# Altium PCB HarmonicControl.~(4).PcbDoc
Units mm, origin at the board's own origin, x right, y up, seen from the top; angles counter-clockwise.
Board outline 133.86 x 40.01 mm, 2 copper layers (Top Layer, Bottom Layer); 10 components, 14 nets, 56 pads, 1 vias.
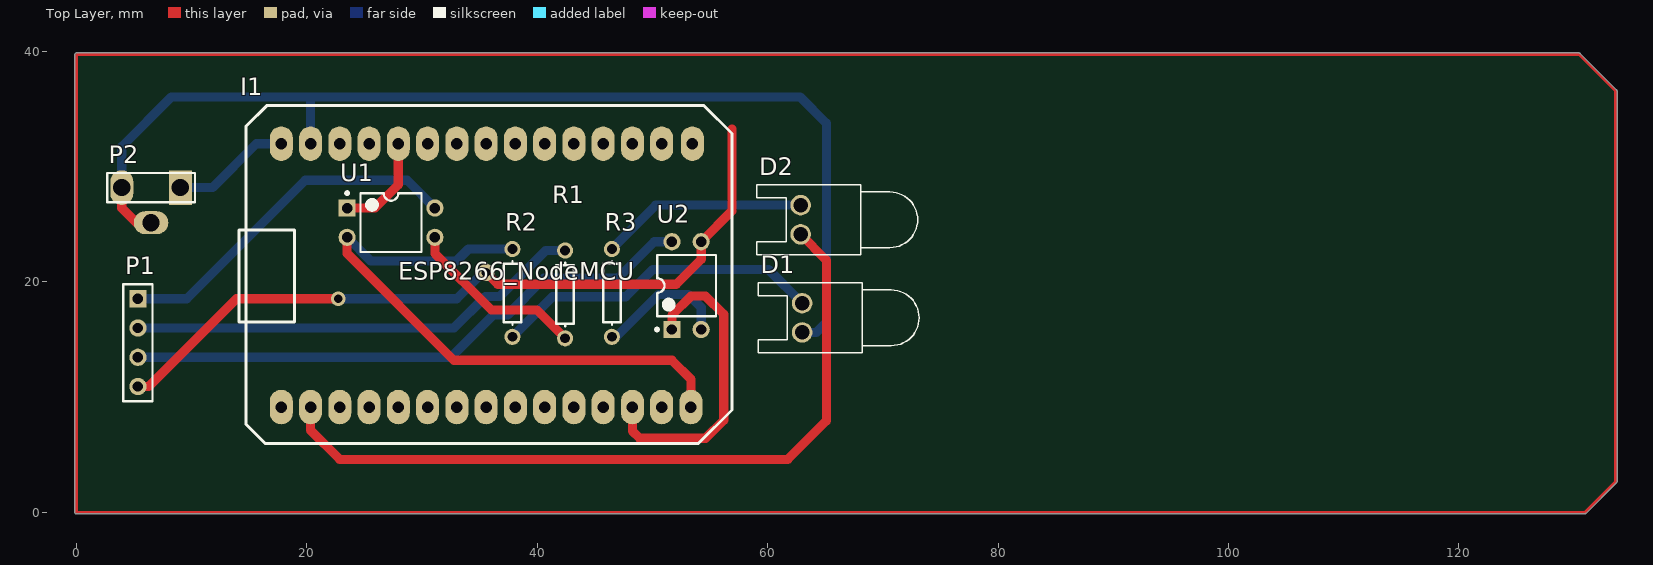
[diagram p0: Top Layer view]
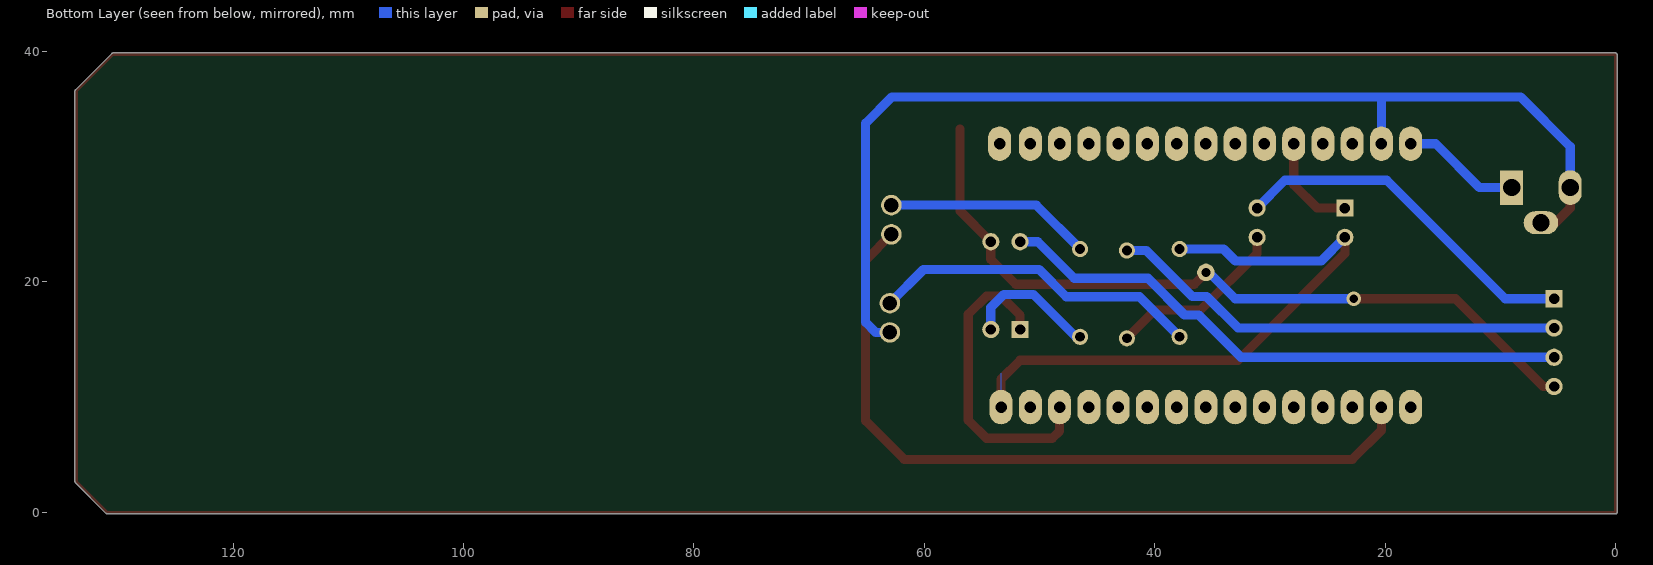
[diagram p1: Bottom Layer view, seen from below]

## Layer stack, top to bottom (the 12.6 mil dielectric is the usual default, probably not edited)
Top Solder: solder mask 0.0102, Solder Resist, Dk 3.5
Top Layer: signal copper 0.0356
Dielectric 1: dielectric 0.32, FR-4, Dk 4.8
Bottom Layer: signal copper 0.0356
Bottom Solder: solder mask 0.0102, Solder Resist, Dk 3.5

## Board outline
0.064,-0.11 cw(c0,0) -0.127,0 -0.127,39.751 cw(c0,39.751) 0,39.878 130.429,39.878 cw(c130.429,39.751) 130.52,39.841 130.519,39.841 133.694,36.666 133.694,36.667 cw(c133.604,36.576) 133.731,36.576 133.731,2.667 cw(c133.604,2.667) 133.694,2.576 133.694,2.577 131.027,-0.09 131.028,-0.09 cw(c130.937,0) 130.937,-0.127 0.127,-0.127 cw(c0.127,0)

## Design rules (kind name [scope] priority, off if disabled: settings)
Clearance [All] p1: gap=0.8 ignorepadtopadclearanceinfootprint=FALSE
PolygonConnect [All] p1: connectstyle=Relief reliefconductorwidth=0.254 reliefentries=4 polygonreliefangle="90 Angle" airgapwidth=0.254
RoutingVias [All] p1: holewidth=0.711 width=1.27 viastyle="Through Hole" minholewidth=0.711 minwidth=1.27 maxholewidth=0.711 maxwidth=1.27
SolderMaskExpansion [All] p1: expansion=0.102
Width [All] p1: maxlimit=1 minlimit=0.5 preferedwidth=0.8
30 further rules are at their usual default settings.

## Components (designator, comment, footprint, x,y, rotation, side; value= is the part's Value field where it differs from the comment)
D1 "LED0" LED-0 62.992,16.891 r90 top
D2 "LED0" LED-0 62.865,25.4 r90 top
I1 "ESP8266" ESP8266_Node_MCU_V3 17.78,32.004 r270 top
P1 "Cable" HDR1X4 5.334,18.542 r270 top
P2 "Jack3.5mm" HDR1X3 9.017,28.194 r180 top
R1 "Res1" AXIAL-0.3 42.418,18.923 r90 top value=1K
R2 "Res1" AXIAL-0.3 37.846,19.05 r270 top value=1K
R3 "Res1" AXIAL-0.3 46.482,19.05 r270 top value=1K
U1 "InputSignal" DIP-4 27.305,25.146 r0 top
U2 "Output_Control" DIP-4 52.959,19.685 r90 top

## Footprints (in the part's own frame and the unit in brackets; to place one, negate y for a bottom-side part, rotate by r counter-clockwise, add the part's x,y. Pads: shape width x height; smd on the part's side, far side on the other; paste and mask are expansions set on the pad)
AXIAL-0.3 [mm] "Axial Device, Thru-Hole; 2 Leads; 0.3 in Pin Spacing"
  round 1.4 hole 0.85: 1(-3.81,0) 2(3.81,0)
  silkscreen extent -2.77,-0.76 2.77,0.76
DIP-4 [mm] "DIP; 4 Leads; Row Spacing 7.62 mm; Pitch 2.54 mm"
  rect 1.5x1.5 hole 0.9: 1(-3.81,1.27)
  round 1.5 hole 0.9: 2(-3.81,-1.27) 3(3.81,-1.27) 4(3.81,1.27)
  silkscreen extent -3.93,-2.55 2.65,2.69, body extent -3.15,-2.5 3.15,2.5, height 5.6
ESP8266_Node_MCU_V3 [mm]
  oval 3x2 hole 1 paste+0 mask+0.102: 1(22.86,35.56) 2(22.86,33.02) 3(22.86,30.48) 4(22.86,27.94) 5(22.86,25.4) 6(22.86,22.86) 7(22.86,20.32) 8(22.86,17.78) 9(22.86,15.24) 10(22.86,12.7) 11(22.86,10.16) 12(22.86,7.62) 13(22.86,5.08) 14(22.86,2.54) 15(22.86,0) 16(0,0) 17(0,2.54) 18(0,5.08) 19(0,7.62) 20(0,10.16) 21(0,12.7) 22(0,15.24) 23(0,17.78) 24(0,20.32) 25(0,22.86) 26(0,25.4) 27(0,27.94) 28(0,30.48) 29(0,33.02) 30(0,35.687)
  silkscreen extent -3.3,-3.68 26.04,39.12
HDR1X3 [mm] "Connector; Header; 3 Position"
  rect 2x3 hole 1.5: 1(0,0)
  oval 3x2 hole 1.5: 2(2.54,3.05)
  oval 2x3 hole 1.5: 3(5.08,0)
  silkscreen extent -1.27,-1.27 6.35,1.27
HDR1X4 [mm] "Connector; Header; 4 Position"
  rect 1.5x1.5 hole 0.9: 1(0,0)
  round 1.5 hole 0.9: 2(2.54,0) 3(5.08,0) 4(7.62,0)
  silkscreen extent -1.27,-1.27 8.89,1.27
LED-0 [mil] "LED; 2 Leads"
  round 70 hole 50: 1(50,0) 2(-50,0)
  silkscreen extent -120,-400 120,150

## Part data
D1 D2: "Typical INFRARED GaAs LED"
I1: library part ESP8266_Node_MCU_V3
P1: library part "Header 4", "Header, 4-Pin"
P2: library part "Header 3", "Header, 3-Pin"
R1 R2 R3: "Resistor"
U1 U2: library part Optoisolator1, "4-Pin Phototransistor Optocoupler"

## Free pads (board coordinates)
  round 1.524 hole 0.762: 4(35.56,20.828)

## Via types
v1: diameter 1.27, hole 0.711, Top Layer to Bottom Layer, 1 vias

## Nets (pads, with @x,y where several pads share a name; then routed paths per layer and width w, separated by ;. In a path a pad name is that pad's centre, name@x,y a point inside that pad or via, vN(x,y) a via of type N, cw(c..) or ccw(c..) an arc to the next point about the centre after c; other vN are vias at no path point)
GND: D1.2 I1.17 P2.2 P2.3 | length 96.1
  Top Layer w0.8: P2.3 3.937,26.416 5.209,25.144 P2.2
  Bottom Layer w0.8: P2.3 3.937,31.75 8.255,36.068 20.32,36.068 ; I1.17 20.32,36.068 ; D1.2 64.211,15.621 65.1,16.51 65.1,33.782 62.814,36.068 20.32,36.068
NetD1_1: D1.1 R2.2 | length 28.8
  Bottom Layer w0.8: R2.2 41.326,18.72 47.676,18.72 50.038,21.082 60.071,21.082 D1.1
NetD2_1: D2.1 R3.1 | length 18
  Bottom Layer w0.8: R3.1 50.292,26.67 D2.1
NetD2_2: D2.2 I1.14 | length 66.3
  Top Layer w0.8: I1.14 20.32,7.137 22.86,4.597 61.747,4.597 65.1,7.95 65.1,21.895 D2.2
NetI1_1: I1.1 R2.1 U1.2 | length 56.7
  Top Layer w0.8: U1.2 23.495,22.479 32.766,13.208 51.689,13.208 53.34,11.557 I1.1
  Bottom Layer w0: I1.1 53.34,12.065
  Bottom Layer w0.8: U1.2 25.552,21.819 32.995,21.819 34.036,22.86 R2.1
NetI1_3: I1.3 U2.1 | length 27.2
  Top Layer w0.8: I1.3 48.26,7.061 48.895,6.426 54.61,6.426 56.185,8.001 56.185,17.196 54.61,18.771 53.34,18.771 51.689,17.12 U2.1
NetI1_16: I1.16 P2.1 | length 10.3
  Bottom Layer w0.8: P2.1 11.811,28.194 15.621,32.004 I1.16
NetI1_20: I1.20 U1.1 | length 8.8
  Top Layer w0.8: U1.1 25.908,26.416 27.94,28.448 I1.20
NetP1_1: P1.1 U1.4 | length 31
  Bottom Layer w0.8: P1.1 9.576,18.542 19.863,28.829 28.702,28.829 U1.4
NetP1_2: P1.2 R1.2 | length 39.9
  Bottom Layer w0.8: P1.2 32.766,16.002 35.504,18.74 36.749,18.74 40.742,22.733 R1.2
NetP1_3: P1.3 U2.4 | length 50.5
  Bottom Layer w0.8: P1.3 32.512,13.462 36.19,17.14 37.411,17.14 40.591,20.32 46.99,20.32 50.165,23.495 U2.4
NetP1_4: P1.4 pad.4 U2.3 | length 66.3
  Top Layer w0.8: P1.4 6.274,10.922 13.894,18.542 v1(22.733,18.542) ; pad.4 36.576,19.812 52.07,19.812 54.229,21.971 U2.3 56.896,26.162 56.896,33.274
  Bottom Layer w0.8: v1(22.733,18.542) 33.02,18.542 pad.4@35.179,20.701
NetR1_1: R1.1 U1.3 | length 15.8
  Top Layer w0.8: U1.3 31.115,22.479 36.017,17.577 39.954,17.577 R1.1
NetR3_2: R3.2 U2.2 | length 12
  Bottom Layer w0: R3.2 R3.2@46.736,15.494
  Bottom Layer w0.8: R3.2 46.863,15.24 50.546,18.923 53.086,18.923 54.229,17.78 U2.2
pads on no net: I1.2 I1.4 I1.5 I1.6 I1.7 I1.8 I1.9 I1.10 I1.11 I1.12 I1.13 I1.15 I1.18 I1.19 I1.21 I1.22 I1.23 I1.24 I1.25 I1.26 I1.27 I1.28 I1.29 I1.30
copper on no net: | length 343.2
  Top Layer w0.254: 0,0 0,39.751 130.429,39.751 133.604,36.576 133.604,2.667 130.937,0 0.127,0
